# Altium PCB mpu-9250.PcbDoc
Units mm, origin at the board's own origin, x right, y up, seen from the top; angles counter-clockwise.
Board outline 66.04 x 76.71 mm, 2 copper layers (Top Layer, Bottom Layer); 15 components, 30 nets, 184 pads, 8 vias.
Unrouted connection lines stored in the file: 7.
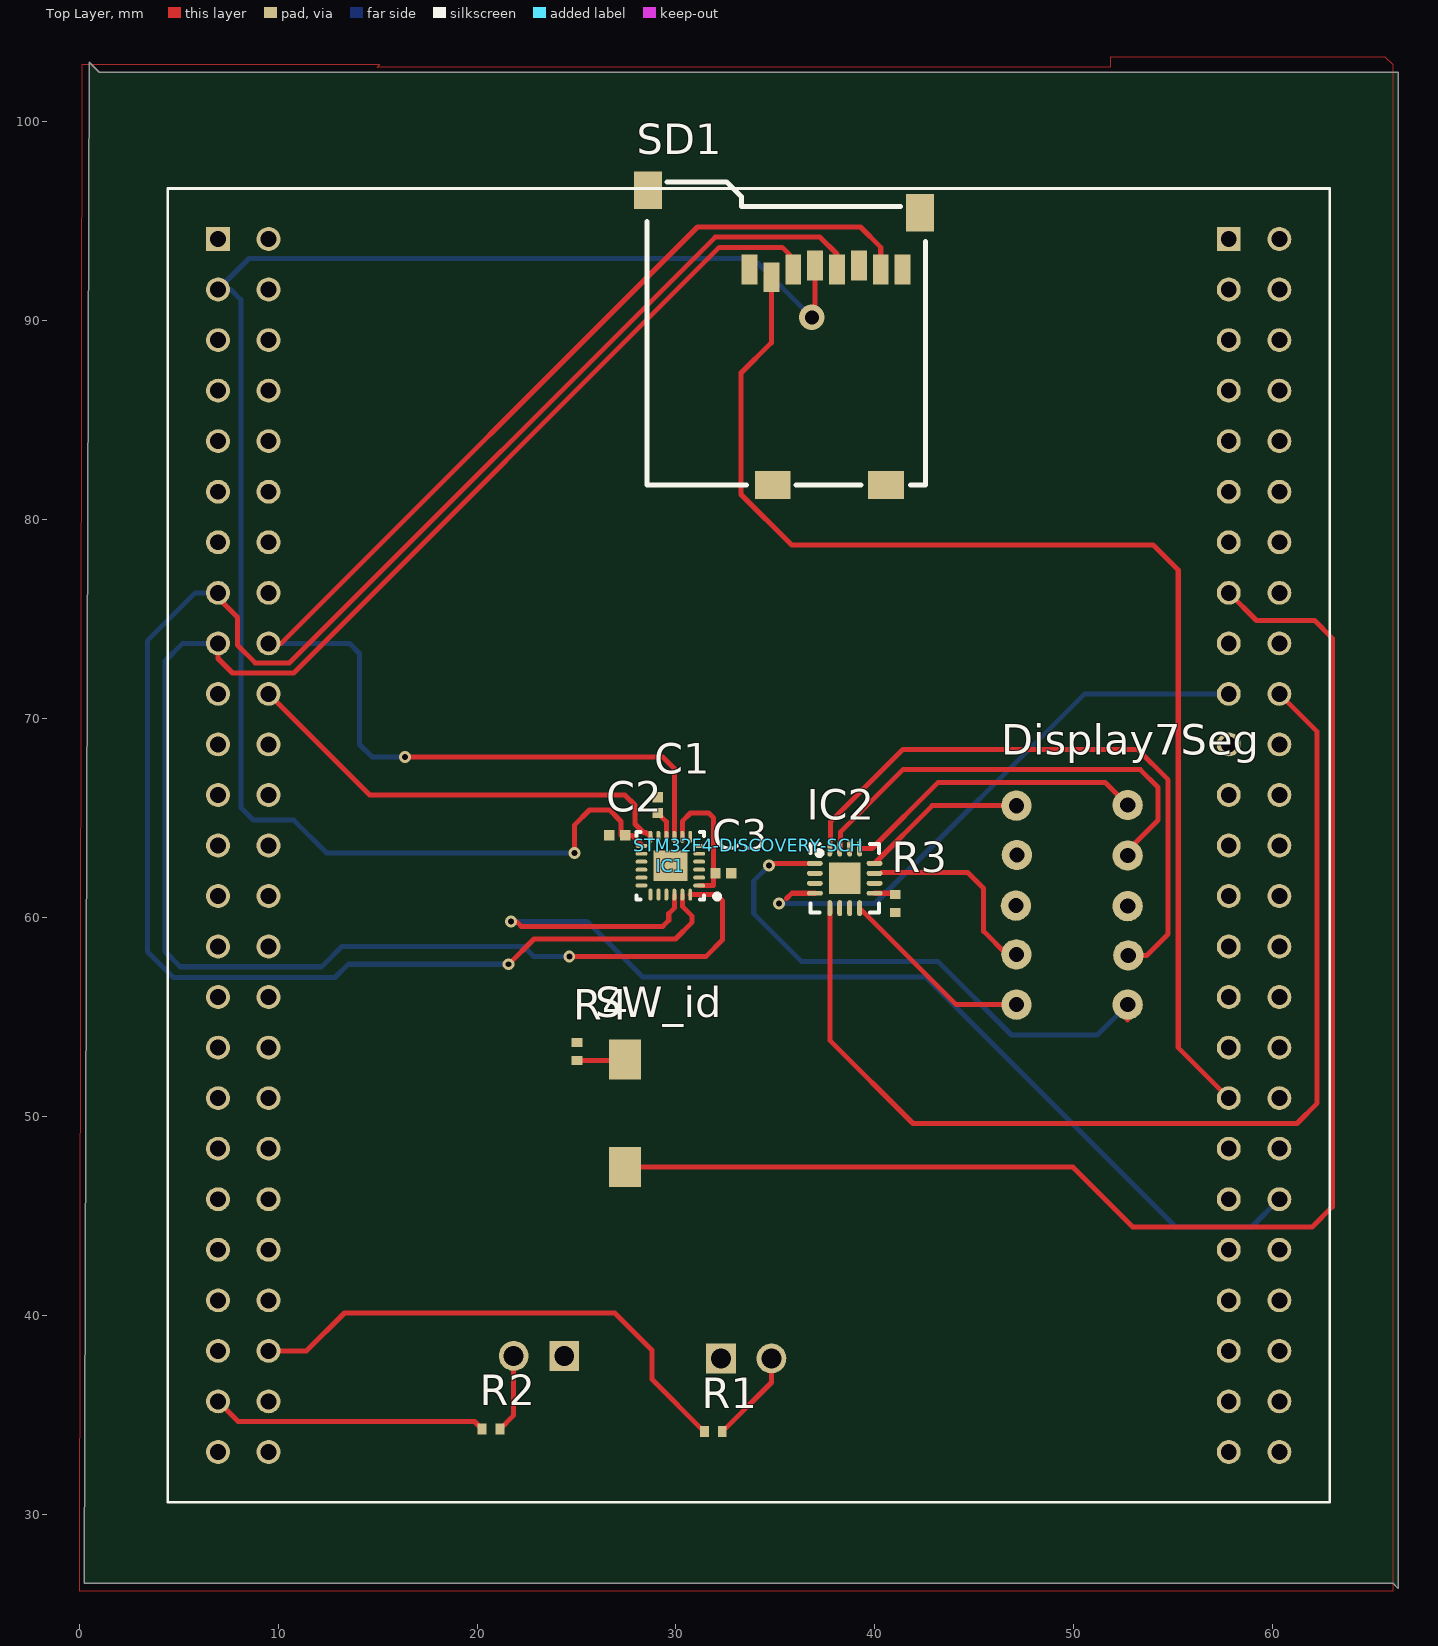
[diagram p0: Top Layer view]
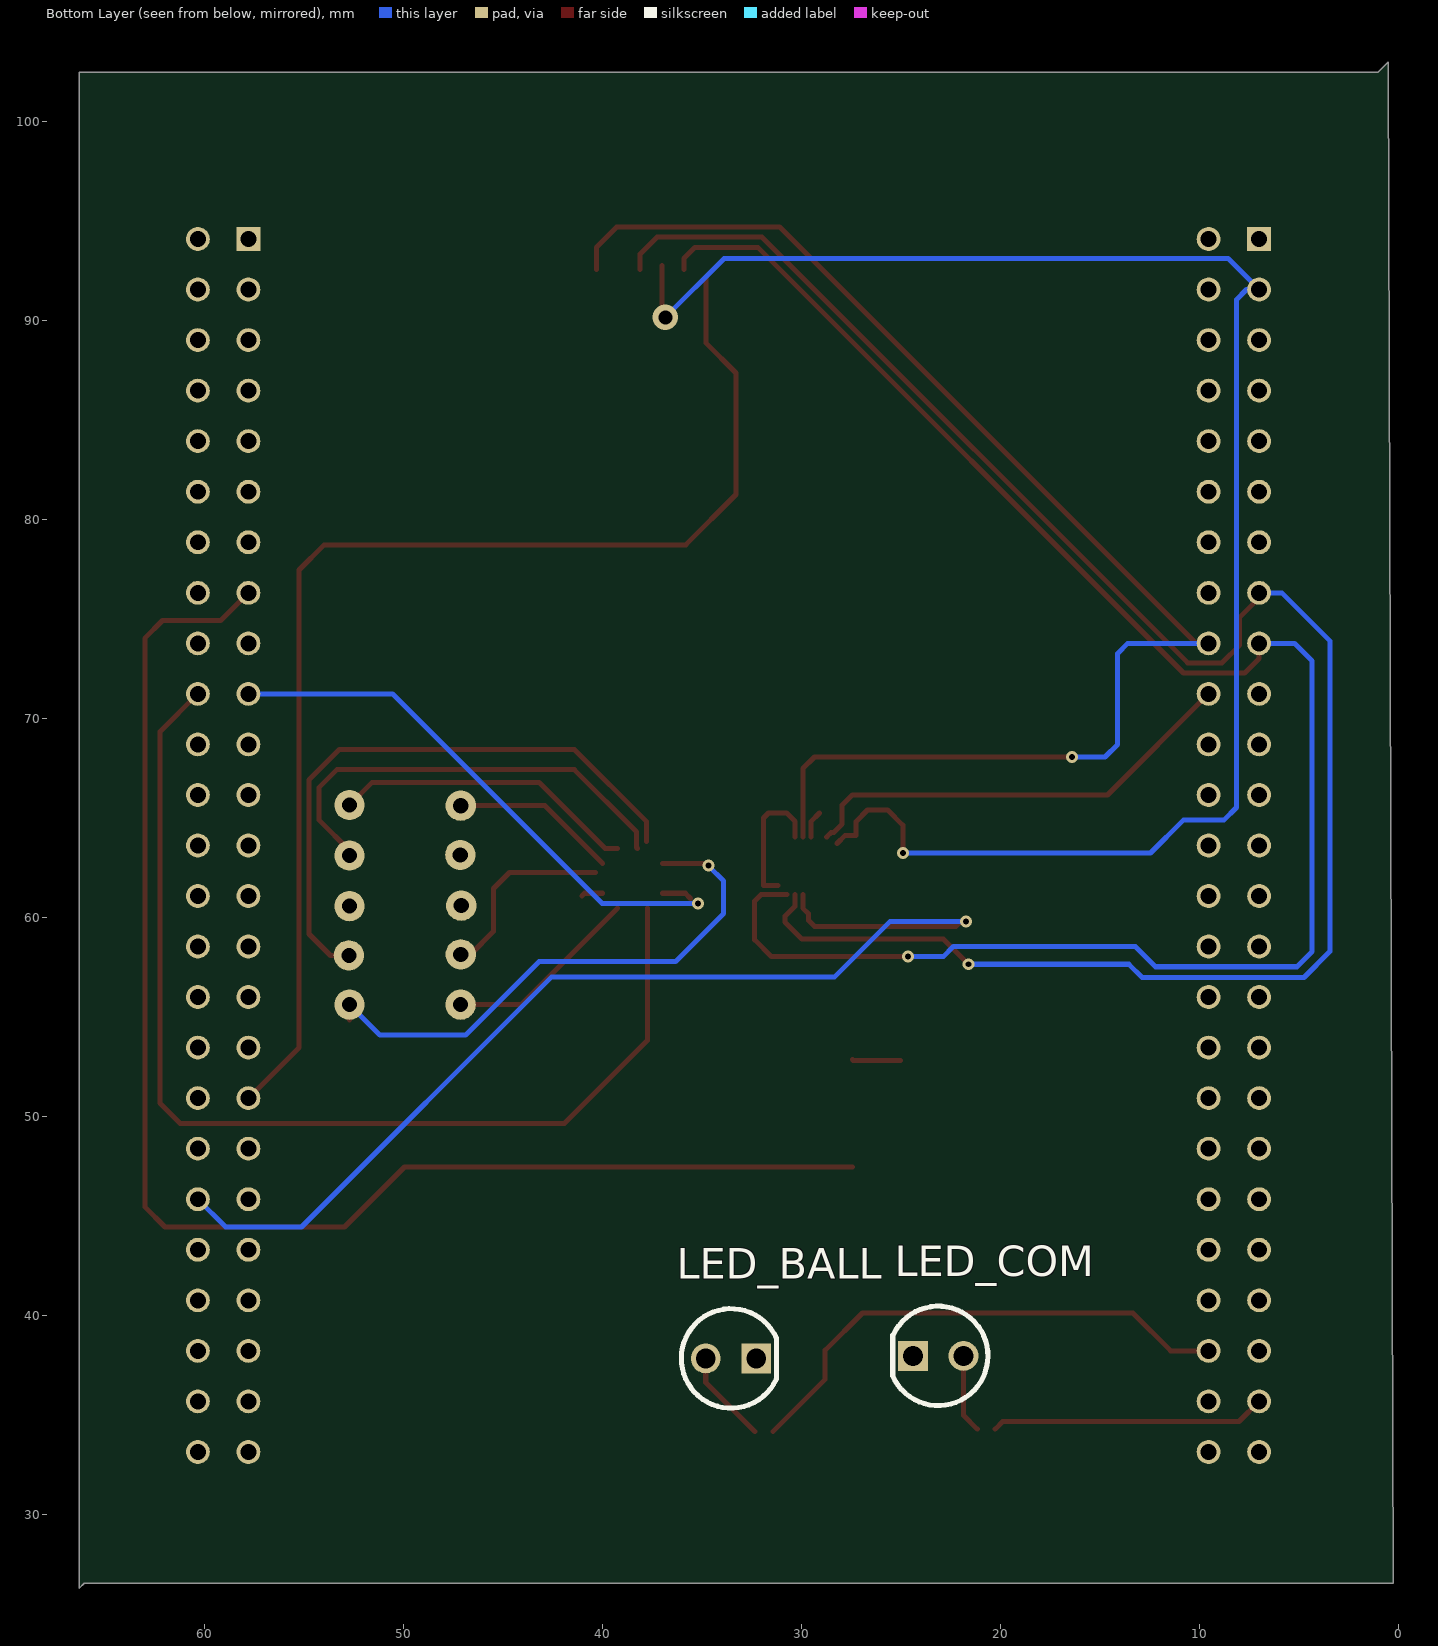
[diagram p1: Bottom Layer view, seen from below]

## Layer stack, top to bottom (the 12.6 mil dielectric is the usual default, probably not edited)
Top Solder: solder mask 0.0102, Solder Resist, Dk 3.5
Top Layer: signal copper 0.0356
Dielectric 1: dielectric 0.32, FR-4, Dk 4.8
Bottom Layer: signal copper 0.0356
Bottom Solder: solder mask 0.0102, Solder Resist, Dk 3.5

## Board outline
0.508,102.997 1.016,102.489 66.294,102.489 66.294,26.289 66.04,26.543 0.254,26.543

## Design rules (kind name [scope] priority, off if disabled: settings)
Clearance [All] p1: gap=0.254 ignorepadtopadclearanceinfootprint=FALSE except(0: Arc-Hole Track-Hole SMDPad-Hole THPad-Hole Via-Hole Fill-Hole Poly-Hole Region-Hole Text-Hole; 0.2: Arc-SMDPad Track-SMDPad SMDPad-SMDPad)
PolygonConnect [All] p1: connectstyle=Relief reliefconductorwidth=0.254 reliefentries=4 polygonreliefangle="90 Angle" airgapwidth=0.254
RoutingVias [All] p1: holewidth=0.711 width=1.27 viastyle="Through Hole" minholewidth=0.711 minwidth=1.27 maxholewidth=0.711 maxwidth=1.27
SolderMaskExpansion [All] p1: expansion=0.102
Width [All] p1: maxlimit=0.254 minlimit=0.254 preferedwidth=0.254
30 further rules are at their usual default settings.

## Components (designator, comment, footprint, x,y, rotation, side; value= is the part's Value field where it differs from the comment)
C1 "100nF" 0402-CAP 29.083,65.659 r90 top value=100n
C2 "100nF" 0402-CAP 27.051,64.135 r180 top value=100n
C3 "1uF" 0402-CAP 32.385,62.23 r0 top value=1u
Display7Seg "HDSP-F513" "New footprint 1"#1 49.911,60.452 r180 top
IC1 "MPU-9250" MPU-9250 29.718,62.611 r180 top
IC2 "STMPE811QTR" QFN16_N 38.481,61.976 r0 top
LED_BALL "LED" LED-5MM-PCB 33.528,37.846 r180 bottom
LED_COM "LED" LED-5MM-PCB 23.114,37.973 r0 bottom
R1 "330R" 0402-RES-HD 31.877,34.163 r0 top value=330
R2 "330R" 0402-RES-HD 20.701,34.29 r0 top value=330
R3 "10K" 0402-RES-HD 41.021,60.706 r270 top
R4 "10K" 0402-RES-HD 25.019,53.271 r90 top
SD1 "2908-05WB-MG" "New footprint 1"#2 35.433,89.154 r0 top
STM32F4-DISCOVERY-SCH "STM32F4-DISCOVERY-SCH" STM32F4-DISCOVERY-PCB 33.655,63.627 r0 top locked
SW_id "SWITCH TACTILE 6 x 3.5 x 4.3 mm" PCBComponent 27.432,50.165 r90 top

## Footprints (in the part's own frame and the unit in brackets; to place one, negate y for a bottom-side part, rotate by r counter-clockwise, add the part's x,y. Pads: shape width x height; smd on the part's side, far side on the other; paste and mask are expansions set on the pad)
0402-CAP [mm] "Chip Capacitor, Body 1.0x0.5mm, Height 0.6mm, IPC Medium Density"
  rect 0.52x0.52 smd: 1(-0.4,0) 2(0.4,0)
  body extent -0.55,-0.3 0.55,0.3, height 0.33
0402-RES-HD [mm] "Chip Resistor, Body 1.0x0.5mm, IPC High Density"
  rect 0.45x0.55 smd: 1(-0.45,0) 2(0.45,0)
  body extent -0.52,-0.27 0.53,0.28, height 0.4
LED-5MM-PCB [mm]
  rect 1.5x1.5 hole 1: 1(1.27,0)
  round 1.5 hole 1: 2(-1.27,0)
  silkscreen extent -2.5,-2.5 2.28,2.5, body extent -2.98,-3.01 2.44,3.01, height 8.59
MPU-9250 [mm] "IMU ACCEL/GYRO/MAG I2C/SPI 24QFN"
  oval 0.6x0.2 smd: 1(-1.45,1) 2(-1.45,0.6) 3(-1.45,0.2) 4(-1.45,-0.2) 5(-1.45,-0.6) 6(-1.45,-1) 13(1.45,-1) 14(1.45,-0.6) 15(1.45,-0.2) 16(1.45,0.2) 17(1.45,0.6) 18(1.45,1)
  oval 0.2x0.6 smd: 7(-1,-1.45) 8(-0.6,-1.45) 9(-0.2,-1.45) 10(0.2,-1.45) 11(0.6,-1.45) 12(1,-1.45) 19(1,1.45) 20(0.6,1.45) 21(0.2,1.45) 22(-0.2,1.45) 23(-0.6,1.45) 24(-1,1.45)
  rect 1.7x1.54 smd: 18(0,0)
  silkscreen extent -2.48,-1.7 1.7,1.7, body extent -1.55,-1.55 1.55,1.55, height 1.05
"New footprint 1"#1 [mil]
  round 60 hole 30: 1(-110,190) 2(-111.22,92.52) 3(-110,-5) 4(-110,-105) 5(-110,-205) 6(110,190) 7(110.24,90.55) 8(111.22,-5.91) 9(109.25,-106.3) 10(110.24,-203.74)
  body extent -149,-255 150,245, height 283
"New footprint 1"#2 [mil]
  rect 31.5x59.06 smd: 1(-68.5,135.04) 2(-25.2,119.29) 3(18.11,135.04) 4(61.42,142.91) 5(104.72,135.04) 6(148.03,142.91) 7(191.34,135.04) 8(234.65,135.04)
  rect 55.12x74.8 smd: M1(269.29,246.85) M2(-269.29,291.73)
  rect 70.87x55.12 smd: M3(201.97,-291.73) M4(-22.44,-291.73)
  silkscreen extent -271,-292 280,308, body extent -269,-292 282,309, height 75
PCBComponent [mm]
  rect 2x1.6 smd: 1(-2.7,0) 2(2.7,0)
  body extent -3.65,-1.75 3.65,1.75, height 5
QFN16_N [mm] "QFN, 16-Leads, Body 3x3mm, Pitch 0.5mm, Thermal Pad 1.6x1.6mm, IPC Medium Density"
  oval 0.8x0.25 smd: 1(-1.5,0.75) 2(-1.5,0.25) 3(-1.5,-0.25) 4(-1.5,-0.75) 9(1.5,-0.75) 10(1.5,-0.25) 11(1.5,0.25) 12(1.5,0.75)
  oval 0.25x0.8 smd: 5(-0.75,-1.5) 6(-0.25,-1.5) 7(0.25,-1.5) 8(0.75,-1.5) 13(0.75,1.5) 14(0.25,1.5) 15(-0.25,1.5) 16(-0.75,1.5)
  rect 1.6x1.6 smd: TH(0,0)
  silkscreen extent -1.73,-1.73 1.73,1.73, body extent -1.58,-1.58 1.58,1.58, height 1
STM32F4-DISCOVERY-PCB [mil]
  rect 47.25x47.25 hole 31.5: P1_1(-1050,1200) P2_1(950,1200)
  round 47.25 hole 31.5: P1_2(-950,1200) P1_3(-1050,1100) P1_4(-950,1100) P1_5(-1050,1000) P1_6(-950,1000) P1_7(-1050,900) P1_8(-950,900) P1_9(-1050,800) P1_10(-950,800) P1_11(-1050,700) P1_12(-950,700) P1_13(-1050,600) P1_14(-950,600) P1_15(-1050,500) P1_16(-950,500) P1_17(-1050,400) P1_18(-950,400) P1_19(-1050,300) P1_20(-950,300) P1_21(-1050,200) P1_22(-950,200) P1_23(-1050,100) P1_24(-950,100) P1_25(-1050,0) P1_26(-950,0) P1_27(-1050,-100) P1_28(-950,-100) P1_29(-1050,-200) P1_30(-950,-200) P1_31(-1050,-300) P1_32(-950,-300) P1_33(-1050,-400) P1_34(-950,-400) P1_35(-1050,-500) P1_36(-950,-500) P1_37(-1050,-600) P1_38(-950,-600) P1_39(-1050,-700) P1_40(-950,-700) P1_41(-1050,-800) P1_42(-950,-800) P1_43(-1050,-900) P1_44(-950,-900) P1_45(-1050,-1000) P1_46(-950,-1000) P1_47(-1050,-1100) P1_48(-950,-1100) P1_49(-1050,-1200) P1_50(-950,-1200) P2_2(1050,1200) P2_3(950,1100) P2_4(1050,1100) P2_5(950,1000) P2_6(1050,1000) P2_7(950,900) P2_8(1050,900) P2_9(950,800) P2_10(1050,800) P2_11(950,700) P2_12(1050,700) P2_13(950,600) P2_14(1050,600) P2_15(950,500) P2_16(1050,500) P2_17(950,400) P2_18(1050,400) P2_19(950,300) P2_20(1050,300) P2_21(950,200) P2_22(1050,200) P2_23(950,100) P2_24(1050,100) P2_25(950,0) P2_26(1050,0) P2_27(950,-100) P2_28(1050,-100) P2_29(950,-200) P2_30(1050,-200) P2_31(950,-300) P2_32(1050,-300) P2_33(950,-400) P2_34(1050,-400) P2_35(950,-500) P2_36(1050,-500) P2_37(950,-600) P2_38(1050,-600) P2_39(950,-700) P2_40(1050,-700) P2_41(950,-800) P2_42(1050,-800) P2_43(950,-900) P2_44(1050,-900) P2_45(950,-1000) P2_46(1050,-1000) P2_47(950,-1100) P2_48(1050,-1100) P2_49(950,-1200) P2_50(1050,-1200)
  silkscreen extent -1150,-1300 1150,1300, body extent -1290,-1455 1289,2583, height 854

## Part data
C1 C2: library part CC0402-100nF-A.12, "CAP CER 0.1UF 10V 20% X5R 0402", Part No=VJ0402V104ZXQPBC
C3: library part CC0402-1uF-5, "CAP CER 1UF 6.3V 10% X5R 0402", Part No=JMK105BJ105KV-F
Display7Seg: library part HDSP-F513-01.A.1, "7 segments display"
IC1: library part MPU-9250-1, "IMU ACCEL/GYRO/MAG I2C/SPI 24QFN"
IC2: library part STMPE811QTR-6, "IC TSC I/O EXPAND 8B 16QFN"
LED_BALL LED_COM: library part LED-5MM-3, "LED 5MM PTH"
R1 R2: library part R0402-330R-7, "RES 330 OHM 1/10W 1% 0402 SMD", Part No=ERJ-2RKF3300X
R3 R4: library part R0402-10K-11, "RES 10K OHM 1/10W 1% 0402 SMD", Part No=ERJ-2RKF1002X
SD1: library part 2908-05WB-MG-01.A.1, "CONN MICRO SD CARD PUSH-PUSH R/A"
SW_id: library part 95C04A3GWRT.-1, "GRAYHILL TACT,GW,6X3.5,1800T&R,LF Eight, 160g Operating Force, Gull Wing, RoHS Compliant", Part No=95C04A3GWRT

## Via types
v1: diameter 0.6, hole 0.3, Top Layer to Bottom Layer, 7 vias
v2: diameter 1.27, hole 0.711, Top Layer to Bottom Layer, 1 vias

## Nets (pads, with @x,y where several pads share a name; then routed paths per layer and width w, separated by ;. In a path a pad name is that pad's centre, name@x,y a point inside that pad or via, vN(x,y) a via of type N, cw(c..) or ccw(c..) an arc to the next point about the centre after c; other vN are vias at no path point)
a: Display7Seg.6 IC2.8 | length 9.9
  Top Layer w0.254: IC2.8 44.081,55.626 Display7Seg.6
b: Display7Seg.7 IC2.11 | length 9.7
  Top Layer w0.254: IC2.11@40.34,62.274 44.66,62.274 45.466,61.468 45.466,59.309 46.623,58.152 Display7Seg.7
Blue_led: R2.1 STM32F4-DISCOVERY-SCH.P1_47 | length 13.8
  Top Layer w0.254: STM32F4-DISCOVERY-SCH.P1_47 8.001,34.671 19.87,34.671 R2.1
c: Display7Seg.10 IC2.12 | length 8.3
  Top Layer w0.254: IC2.12 42.882,65.627 Display7Seg.10
d: Display7Seg.5 IC2.13 | length 15.3
  Top Layer w0.254: IC2.13 39.854,63.476 43.18,66.802 51.562,66.802 Display7Seg.5
DP: Display7Seg.9
e: Display7Seg.4 IC2.15 | length 22.5
  Top Layer w0.254: IC2.15 38.279,63.524 38.279,64.314 41.402,67.437 53.34,67.437 54.229,66.548 54.229,64.897 52.705,63.373 Display7Seg.4
f: Display7Seg.2 IC2.16 | length 30.3
  Top Layer w0.254: IC2.16@37.771,63.835 37.771,64.822 41.402,68.453 53.213,68.453 54.737,66.929 54.737,59.182 53.657,58.102 Display7Seg.2
g: Display7Seg.1 IC2.1 | length 27.6
  Top Layer w0.254: v1@34.81,62.726 IC2.1 ; 52.705,54.864 Display7Seg.1
  Bottom Layer w0.254: v1(34.671,62.611) 33.909,61.849 33.909,60.198 36.322,57.785 43.18,57.785 46.863,54.102 51.181,54.102 Display7Seg.1
GND: C1.2 C2.2 C3.2 Display7Seg.3 Display7Seg.8 IC1.11 IC1.18 IC1.20 IC2.3 IC2.10 LED_BALL.1 LED_COM.1 R3.2 R4.2 SD1.6 STM32F4-DISCOVERY-SCH.P1_1 STM32F4-DISCOVERY-SCH.P1_2 STM32F4-DISCOVERY-SCH.P1_5 STM32F4-DISCOVERY-SCH.P1_49 STM32F4-DISCOVERY-SCH.P1_50 STM32F4-DISCOVERY-SCH.P2_1 STM32F4-DISCOVERY-SCH.P2_2 STM32F4-DISCOVERY-SCH.P2_49 STM32F4-DISCOVERY-SCH.P2_50
ID_button: STM32F4-DISCOVERY-SCH.P2_15 SW_id.1 | length 72
  Top Layer w0.254: SW_id.1 49.944,47.465 52.959,44.45 61.976,44.45 62.992,45.466 62.992,74.041 62.103,74.93 59.182,74.93 STM32F4-DISCOVERY-SCH.P2_15
INT_MPU: IC1.12 STM32F4-DISCOVERY-SCH.P1_20 | length 22.7
  Top Layer w0.254: STM32F4-DISCOVERY-SCH.P1_20 14.605,66.167 27.432,66.167 27.94,65.659 27.94,64.707 28.364,64.283 28.496,64.283 IC1.12
MISO: IC1.9 SD1.7 STM32F4-DISCOVERY-SCH.P1_18 | length 70.1
  Top Layer w0.254: STM32F4-DISCOVERY-SCH.P1_18 10.16,73.787 31.081,94.708 39.277,94.708 40.293,93.692 SD1.7 ; v1(16.383,68.072) 29.337,68.072 29.918,67.491 IC1.9
  Bottom Layer w0.254: STM32F4-DISCOVERY-SCH.P1_18 13.589,73.787 14.097,73.279 14.097,68.707 14.732,68.072 v1(16.383,68.072)
MOSI: IC1.24 SD1.3 STM32F4-DISCOVERY-SCH.P1_17 | length 90.3
  Top Layer w0.254: STM32F4-DISCOVERY-SCH.P1_17 6.985,73.025 7.712,72.298 10.786,72.298 32.18,93.692 35.34,93.692 35.893,93.139 SD1.3 ; v1(24.638,58.039) 31.496,58.039 32.339,58.882 32.339,60.833 32.011,61.161 IC1.24
  Bottom Layer w0.254: STM32F4-DISCOVERY-SCH.P1_17 5.207,73.787 4.318,72.898 4.318,58.293 5.08,57.531 12.192,57.531 13.208,58.547 22.352,58.547 22.86,58.039 v1(24.638,58.039)
MPU_CS: IC1.22 STM32F4-DISCOVERY-SCH.P2_40 | length 55.1
  Top Layer w0.254: v1(21.717,59.817) 21.971,59.817 22.225,59.563 29.337,59.563 29.637,59.863 29.637,60.198 29.918,60.479 IC1.22
  Bottom Layer w0.254: v1(21.717,59.817) 25.527,59.817 28.321,57.023 42.545,57.023 55.118,44.45 58.928,44.45 STM32F4-DISCOVERY-SCH.P2_40
NetC1_1: C1.1 IC1.10 | length 1.4
  Top Layer w0.254: C1.1 29.518,64.824 IC1.10
NetC3_1: C3.1 IC1.1 IC1.8 | length 6.8
  Top Layer w0.254: IC1.8 30.318,64.843 30.734,65.259 31.642,65.259 31.893,65.008 31.893,62.084 31.893,61.611 IC1.1
NetIC2_9: IC2.9 R3.1 | length 1.1
  Top Layer w0.254: IC2.9 40.893,61.226 R3.1@41.021,61.098
NetLED_BALL_2: LED_BALL.2 R1.2 | length 4.7
  Top Layer w0.254: R1.2 34.798,36.634 LED_BALL.2
NetLED_COM_2: LED_COM.2 R2.2 | length 4
  Top Layer w0.254: R2.2 21.844,34.983 LED_COM.2
NetR4_1: R4.1 SW_id.2 | length 2.4
  Top Layer w0.254: R4.1 27.388,52.821 SW_id.2
NRF_CE: STM32F4-DISCOVERY-SCH.P1_13
NRF_CS#: STM32F4-DISCOVERY-SCH.P1_16
NRF_IRQ: STM32F4-DISCOVERY-SCH.P1_19
Red_led: R1.1 STM32F4-DISCOVERY-SCH.P1_46 | length 26
  Top Layer w0.254: STM32F4-DISCOVERY-SCH.P1_46 11.43,38.227 13.335,40.132 26.924,40.132 28.795,38.261 28.795,36.795 R1.1
SCK: IC1.23 SD1.5 STM32F4-DISCOVERY-SCH.P1_15 | length 94.4
  Top Layer w0.254: STM32F4-DISCOVERY-SCH.P1_15 6.985,76.073 7.966,75.092 7.966,73.695 8.855,72.806 10.576,72.806 31.97,94.2 37.245,94.2 38.093,93.352 SD1.5 ; v1(21.59,57.658) 22.86,58.928 29.972,58.928 30.815,59.771 30.815,60.071 30.318,60.568 IC1.23
  Bottom Layer w0.254: STM32F4-DISCOVERY-SCH.P1_15 5.842,76.327 3.429,73.914 3.429,58.293 4.734,56.988 12.862,56.988 13.532,57.658 v1(21.59,57.658)
SCL: IC2.4 STM32F4-DISCOVERY-SCH.P2_19 | length 28.5
  Top Layer w0.254: 35.56,60.96 35.826,61.226 IC2.4
  Bottom Layer w0.254: v1(35.179,60.706) 40.005,60.706 50.546,71.247 STM32F4-DISCOVERY-SCH.P2_19
SDA: IC2.5 STM32F4-DISCOVERY-SCH.P2_20 | length 54.7
  Top Layer w0.254: IC2.5 37.731,53.836 41.91,49.657 61.214,49.657 62.23,50.673 62.23,69.342 STM32F4-DISCOVERY-SCH.P2_20
uSD_CS: SD1.2 STM32F4-DISCOVERY-SCH.P2_35 | length 62.7
  Top Layer w0.254: SD1.2 34.793,88.895 33.274,87.376 33.274,81.271 35.805,78.74 53.975,78.74 55.245,77.47 55.245,53.467 STM32F4-DISCOVERY-SCH.P2_35
VDD: C2.1 IC1.13 IC2.6 IC2.14 SD1.4 STM32F4-DISCOVERY-SCH.P1_3 | length 84.9
  Top Layer w0.254: v1(24.892,63.246) 24.892,64.643 25.654,65.405 26.67,65.405 27.238,64.837 27.238,64.135 C2.1 27.794,64.135 28.207,63.722 ; v2@36.993,90.333 SD1.4
  Bottom Layer w0.254: v1(24.892,63.246) 12.446,63.246 10.795,64.897 8.763,64.897 8.128,65.532 8.128,91.059 7.62,91.567 STM32F4-DISCOVERY-SCH.P1_3 8.544,93.126 33.874,93.126 v2(36.83,90.17)
pads on no net: IC1.2 IC1.3 IC1.4 IC1.5 IC1.6 IC1.7 IC1.14 IC1.15 IC1.16 IC1.17 IC1.19 IC1.21 IC2.2 IC2.7 IC2.TH SD1.1 SD1.8 SD1.M1 SD1.M2 SD1.M3 SD1.M4 STM32F4-DISCOVERY-SCH.P1_4 STM32F4-DISCOVERY-SCH.P1_6 STM32F4-DISCOVERY-SCH.P1_7 STM32F4-DISCOVERY-SCH.P1_8 STM32F4-DISCOVERY-SCH.P1_9 STM32F4-DISCOVERY-SCH.P1_10 STM32F4-DISCOVERY-SCH.P1_11 STM32F4-DISCOVERY-SCH.P1_12 STM32F4-DISCOVERY-SCH.P1_14 STM32F4-DISCOVERY-SCH.P1_21 STM32F4-DISCOVERY-SCH.P1_22 STM32F4-DISCOVERY-SCH.P1_23 STM32F4-DISCOVERY-SCH.P1_24 STM32F4-DISCOVERY-SCH.P1_25 STM32F4-DISCOVERY-SCH.P1_26 STM32F4-DISCOVERY-SCH.P1_27 STM32F4-DISCOVERY-SCH.P1_28 STM32F4-DISCOVERY-SCH.P1_29 STM32F4-DISCOVERY-SCH.P1_30 STM32F4-DISCOVERY-SCH.P1_31 STM32F4-DISCOVERY-SCH.P1_32 STM32F4-DISCOVERY-SCH.P1_33 STM32F4-DISCOVERY-SCH.P1_34 STM32F4-DISCOVERY-SCH.P1_35 STM32F4-DISCOVERY-SCH.P1_36 STM32F4-DISCOVERY-SCH.P1_37 STM32F4-DISCOVERY-SCH.P1_38 STM32F4-DISCOVERY-SCH.P1_39 STM32F4-DISCOVERY-SCH.P1_40 STM32F4-DISCOVERY-SCH.P1_41 STM32F4-DISCOVERY-SCH.P1_42 STM32F4-DISCOVERY-SCH.P1_43 STM32F4-DISCOVERY-SCH.P1_44 STM32F4-DISCOVERY-SCH.P1_45 STM32F4-DISCOVERY-SCH.P1_48 STM32F4-DISCOVERY-SCH.P2_3 STM32F4-DISCOVERY-SCH.P2_4 STM32F4-DISCOVERY-SCH.P2_5 STM32F4-DISCOVERY-SCH.P2_6 STM32F4-DISCOVERY-SCH.P2_7 STM32F4-DISCOVERY-SCH.P2_8 STM32F4-DISCOVERY-SCH.P2_9 STM32F4-DISCOVERY-SCH.P2_10 STM32F4-DISCOVERY-SCH.P2_11 STM32F4-DISCOVERY-SCH.P2_12 STM32F4-DISCOVERY-SCH.P2_13 STM32F4-DISCOVERY-SCH.P2_14 STM32F4-DISCOVERY-SCH.P2_16 STM32F4-DISCOVERY-SCH.P2_17 STM32F4-DISCOVERY-SCH.P2_18 STM32F4-DISCOVERY-SCH.P2_21 STM32F4-DISCOVERY-SCH.P2_22 STM32F4-DISCOVERY-SCH.P2_23 STM32F4-DISCOVERY-SCH.P2_24 STM32F4-DISCOVERY-SCH.P2_25 STM32F4-DISCOVERY-SCH.P2_26 STM32F4-DISCOVERY-SCH.P2_27 STM32F4-DISCOVERY-SCH.P2_28 STM32F4-DISCOVERY-SCH.P2_29 STM32F4-DISCOVERY-SCH.P2_30 STM32F4-DISCOVERY-SCH.P2_31 STM32F4-DISCOVERY-SCH.P2_32 STM32F4-DISCOVERY-SCH.P2_33 STM32F4-DISCOVERY-SCH.P2_34 STM32F4-DISCOVERY-SCH.P2_36 STM32F4-DISCOVERY-SCH.P2_37 STM32F4-DISCOVERY-SCH.P2_38 STM32F4-DISCOVERY-SCH.P2_39 STM32F4-DISCOVERY-SCH.P2_41 STM32F4-DISCOVERY-SCH.P2_42 STM32F4-DISCOVERY-SCH.P2_43 STM32F4-DISCOVERY-SCH.P2_44 STM32F4-DISCOVERY-SCH.P2_45 STM32F4-DISCOVERY-SCH.P2_46 STM32F4-DISCOVERY-SCH.P2_47 STM32F4-DISCOVERY-SCH.P2_48

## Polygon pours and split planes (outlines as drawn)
GND on Top Layer "gnd top" (solid, shelved, pour order 2): 14.986,26.162 51.689,26.162 66.04,26.162 66.04,102.87 65.659,103.251 51.816,103.251 51.816,102.743 14.986,102.743 15.113,102.87 0.127,102.87 0.002,26.162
